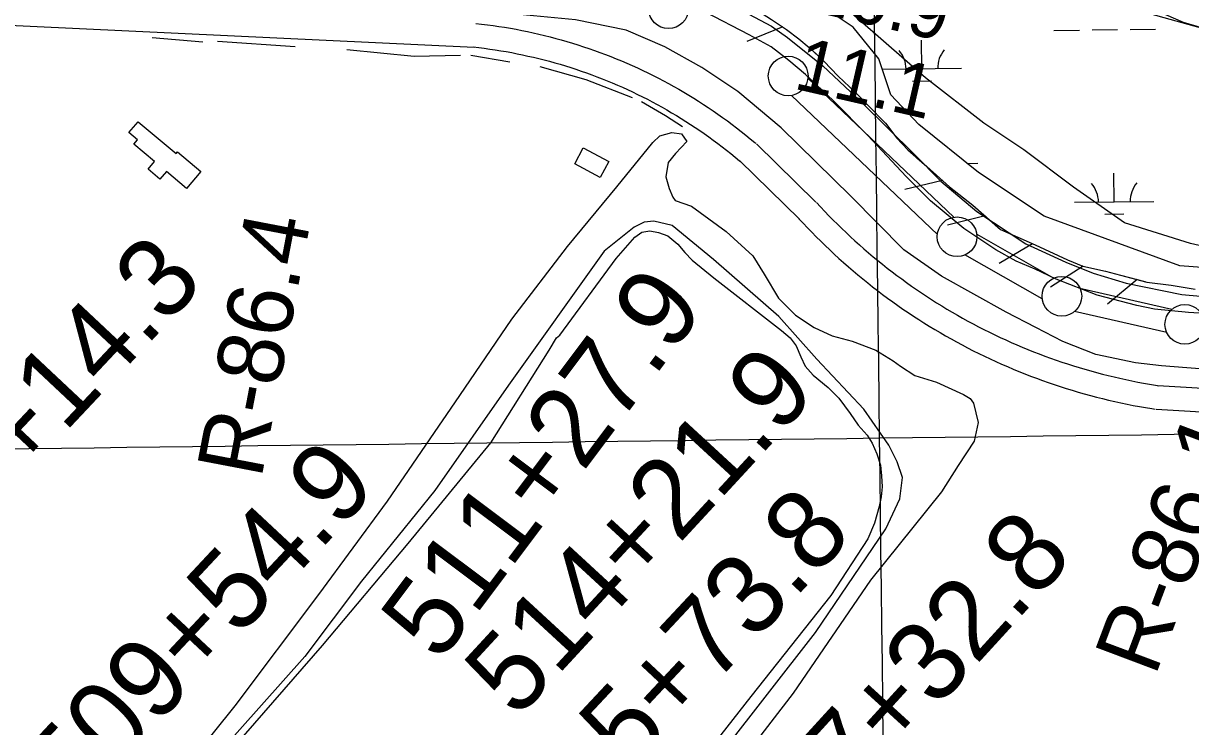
# Model space of a CAD drawing. Extents: x 3704301 to 3742427, y 506229 to 532009.
# Drawn here: x 3723258 to 3724729, y 517533 to 518420 of the extents above; entities that cross this region are included whole.
import ezdxf

# ---------------------------------------------------------------- set-up
doc = ezdxf.new("R2010")
doc.units = 0
for name, color, linetype in [('V-BLDG-OTLN', 7, 'Continuous'), ('V-FLOD-BASE', 7, 'Continuous'), ('V-GRID-MAJR', 7, 'Continuous'), ('V-LEVE-TOET', 7, 'Continuous'), ('V-RIVR-RANG', 7, 'Continuous'), ('V-RIVR-RANG-IDEN', 7, 'Continuous'), ('V-ROAD-CNTR', 7, 'Continuous'), ('V-RRAP-FSHR', 7, 'Continuous'), ('V-SITE-VEGE', 7, 'Continuous'), ('V-SURV-IDEN', 7, 'Continuous'), ('V-SURV-LINE', 7, 'Continuous'), ('V-TOPO-SHOR', 7, 'Continuous'), ('V-WETL-SWMP', 7, 'Continuous')]:
    doc.layers.add(name, color=color, linetype=linetype)

msp = doc.modelspace()

# ---------------------------------------------------------------- linework, layer by layer
at = {"layer": 'V-BLDG-OTLN'}
for points in [[(3723452.231, 518257.636), (3723481.544, 518232.97000000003), (3723463.593, 518211.63800000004), (3723438.376, 518232.86), (3723430.1210000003, 518223.048), (3723415.097, 518235.69200000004), (3723423.432, 518245.596), (3723397.384, 518267.518), (3723401.918, 518272.902), (3723391.08, 518282.022), (3723402.6350000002, 518295.75200000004), (3723450.4450000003, 518255.515)], [(3723963.7290000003, 518262.80100000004), (3723995.7290000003, 518245.715), (3723984.881, 518225.39900000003), (3723952.881, 518242.485)]]:
    msp.add_lwpolyline(points, close=True, dxfattribs=at)
at = {"layer": 'V-FLOD-BASE'}
msp.add_lwpolyline([(3724820.361, 518049.058), (3724726.697, 518055.04600000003), (3724683.724, 518059.281), (3724661.614, 518063.777), (3724611.377, 518076.86100000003), (3724559.861, 518097.085), (3724533.473, 518109.871), (3724509.507, 518119.708), (3724483.694, 518134.289), (3724443.418, 518161.21), (3724401.262, 518195.856), (3724370.481, 518226.472), (3724322.148, 518278.327), (3724278.679, 518322.496), (3724243.6950000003, 518355.443), (3724222.613, 518373.064), (3724200.345, 518390.074), (3724172.736, 518405.23000000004), (3724117.538, 518433.754)], dxfattribs=at)
at = {"layer": 'V-GRID-MAJR'}
for points in [[(3724411.217, 511839.73000000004), (3724337.211, 517896.76900000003), (3724263.162, 523957.275), (3724189.114, 530017.796), (3724189.072, 530021.25)], [(3708498.534, 517706.704), (3713778.102, 517769.291), (3719057.661, 517832.646), (3724337.211, 517896.76900000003), (3729616.752, 517961.659), (3734896.2830000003, 518027.318), (3740175.804, 518093.744), (3740175.805, 518093.744)]]:
    msp.add_spline(points, degree=3, dxfattribs=at)
at = {"layer": 'V-LEVE-TOET'}
for points in [[(3723241.023, 518548.99700000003), (3723399.696, 518540.24), (3723580.989, 518534.147), (3723761.02, 518523.86600000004), (3723846.936, 518517.77900000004), (3723929.855, 518512.85000000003), (3723964.483, 518508.51), (3723996.7430000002, 518502.952), (3724037.412, 518492.13), (3724078.714, 518478.337), (3724135.684, 518451.02900000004), (3724201.095, 518416.074), (3724220.9420000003, 518402.014), (3724265.498, 518366.205)], [(3724831.0330000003, 517976.94200000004), (3724692.602, 517987.739), (3724659.769, 517991.505), (3724609.562, 518002.206), (3724568.231, 518018.385), (3724534.077, 518036.147), (3724496.879, 518055.35500000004), (3724415.244, 518100.837), (3724367.736, 518134.226), (3724300.728, 518201.945), (3724213.225, 518287.889), (3724158.4080000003, 518333.70300000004), (3724113.323, 518364.143), (3724066.5, 518390.386), (3724017.9560000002, 518411.24), (3723954.014, 518424.157), (3723865.683, 518432.597), (3723729.741, 518435.079), (3723574.071, 518442.087), (3723411.247, 518449.006), (3723312.265, 518451.353), (3723185.225, 518456.927)], [(3724265.498, 518366.205), (3724314.353, 518320.315), (3724381.339, 518254.384), (3724414.543, 518220.819), (3724459.724, 518182.634), (3724521.633, 518141.674), (3724571.9960000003, 518118.456), (3724606.265, 518104.577), (3724648.148, 518091.982), (3724718.0670000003, 518077.949), (3724798.037, 518070.597), (3724933.466, 518061.55100000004), (3725125.861, 518054.284), (3725305.761, 518044.956), (3725459.773, 518037.212), (3725587.4080000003, 518031.646), (3725746.0810000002, 518022.886), (3725925.011, 518014.977), (3725985.8340000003, 518013.349)]]:
    msp.add_lwpolyline(points, dxfattribs=at)
at = {"layer": 'V-ROAD-CNTR'}
for points in [[(3722128.416704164, 518470.75203230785), (3722271.2194185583, 518463.91704597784), (3723825.9983089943, 518389.90419400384)], [(3723828.404304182, 518419.7911342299), (3723835.593289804, 518418.9751358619), (3723842.8572752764, 518418.0671376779), (3723850.107260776, 518417.077139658), (3723857.348246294, 518416.0081417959), (3723864.576231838, 518414.85614409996), (3723871.788217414, 518413.6251465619), (3723878.9902030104, 518412.3131491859), (3723886.17518864, 518410.9201519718), (3723893.343174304, 518409.447154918), (3723900.497159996, 518407.893158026), (3723907.63014573, 518406.26016129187), (3723914.7451315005, 518404.548164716), (3723921.842117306, 518402.75616829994), (3723928.9181031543, 518400.8841720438), (3723935.9710890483, 518398.933175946), (3723943.002074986, 518396.9041800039), (3723950.0110609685, 518394.7961842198), (3723956.9970469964, 518392.610188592), (3723963.9560330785, 518390.34519312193), (3723970.8890192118, 518388.00419780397), (3723977.796005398, 518385.5842026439), (3723984.6769916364, 518383.0882076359), (3723991.527977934, 518380.5152127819), (3723998.351964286, 518377.865218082), (3724005.1429507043, 518375.138223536), (3724011.9029371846, 518372.338229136), (3724018.6339237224, 518369.4602348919), (3724025.330910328, 518366.50724079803), (3724031.993897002, 518363.4802468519), (3724038.6228837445, 518360.3792530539), (3724045.217870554, 518357.204259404), (3724051.7758574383, 518353.954265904), (3724058.2968443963, 518350.6332725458), (3724064.7788314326, 518347.23827933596), (3724071.2248185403, 518343.772286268), (3724077.6318057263, 518340.2322933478), (3724083.998792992, 518336.62130057), (3724090.323780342, 518332.9403079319), (3724096.6077677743, 518329.1883154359), (3724102.848755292, 518325.36632307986), (3724109.046742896, 518321.474330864), (3724115.201730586, 518317.5133387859), (3724121.3107183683, 518313.48434684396), (3724127.3757062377, 518309.38735503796), (3724133.3946942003, 518305.22136336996), (3724139.3656822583, 518300.9893718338), (3724145.287670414, 518296.69138043), (3724151.162658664, 518292.32638915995), (3724156.988647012, 518287.89639802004), (3724162.76463546, 518283.40140700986), (3724168.48962401, 518278.8424161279), (3724174.1636126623, 518274.21842537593), (3724179.758601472, 518269.55443470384), (3724181.0385989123, 518268.47343686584)], [(3723825.0183109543, 518389.983193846), (3723832.0392969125, 518389.185195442), (3723838.967283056, 518388.31919717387), (3723845.887269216, 518387.3751990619), (3723852.796255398, 518386.3542011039), (3723859.692241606, 518385.2562033), (3723866.576227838, 518384.0812056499), (3723873.446214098, 518382.829208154), (3723880.301200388, 518381.50021081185), (3723887.141186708, 518380.09521362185), (3723893.9651730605, 518378.6132165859), (3723900.772159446, 518377.05421970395), (3723907.5631458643, 518375.42022297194), (3723914.332132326, 518373.710226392), (3723921.082118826, 518371.92422996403), (3723927.813105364, 518370.06323368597), (3723934.524091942, 518368.12623755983), (3723941.211078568, 518366.11624158), (3723947.8730652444, 518364.03024575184), (3723954.514051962, 518361.8692500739), (3723961.1310387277, 518359.63425454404), (3723967.7220255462, 518357.32625915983), (3723974.287012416, 518354.9442639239), (3723980.823999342, 518352.4892688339), (3723987.3319863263, 518349.96127389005), (3723993.812973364, 518347.36027909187), (3724000.2649604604, 518344.6862844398), (3724006.685947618, 518341.942289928), (3724013.07493484, 518339.12529556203), (3724019.433922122, 518336.2363013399), (3724025.7589094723, 518333.27730725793), (3724032.0498968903, 518330.24831331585), (3724038.3058843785, 518327.148319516), (3724044.528871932, 518323.9773258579), (3724050.7168595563, 518320.73833233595), (3724056.866847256, 518317.4303389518), (3724062.9778350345, 518314.05434570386), (3724069.052822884, 518310.6093525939), (3724075.087810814, 518307.09635961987), (3724081.0837988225, 518303.5163667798), (3724087.038786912, 518299.8703740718), (3724092.952775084, 518296.1563815), (3724098.8257633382, 518292.3773890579), (3724104.6547516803, 518288.53239674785), (3724110.4417401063, 518284.62340456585), (3724116.1827286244, 518280.649412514), (3724121.87971723, 518276.6114205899), (3724127.531705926, 518272.5094287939), (3724133.1386947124, 518268.34443712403), (3724138.6966835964, 518264.11844557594), (3724144.2066725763, 518259.829454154), (3724149.6696616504, 518255.47846285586), (3724155.0836508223, 518251.06847167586), (3724160.4726400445, 518246.57448066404), (3724161.6786376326, 518245.55548270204)], [(3724181.8415973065, 518267.7434383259), (3724256.98944701, 518194.3175851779)], [(3724160.8756392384, 518246.28548124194), (3724236.023488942, 518172.85962809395)], [(3724257.513445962, 518193.778586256), (3724262.7364355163, 518188.13659753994), (3724267.9644250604, 518182.6066085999), (3724273.251414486, 518177.12861955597), (3724278.592403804, 518171.70563040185), (3724283.988393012, 518166.3376411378), (3724289.441382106, 518161.02665175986), (3724294.948371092, 518155.770662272), (3724300.508359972, 518150.572672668), (3724306.1213487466, 518145.43168295), (3724311.786337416, 518140.3496931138), (3724317.505325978, 518135.32570316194), (3724323.275314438, 518130.36071309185), (3724329.0953027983, 518125.45572290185), (3724334.965291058, 518120.61173258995), (3724340.887279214, 518115.82674215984), (3724346.8562672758, 518111.103751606), (3724352.8732552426, 518106.44276092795), (3724358.938243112, 518101.84477012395), (3724365.051230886, 518097.30777919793), (3724371.210218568, 518092.83478814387), (3724377.41420616, 518088.42579696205), (3724383.66419366, 518084.0808056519), (3724389.9581810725, 518079.79881421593), (3724396.295168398, 518075.584822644), (3724402.676155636, 518071.4348309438), (3724409.09914279, 518067.35083911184), (3724415.56412986, 518063.33284714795), (3724422.071116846, 518059.38185504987), (3724428.617103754, 518055.497862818), (3724435.203090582, 518051.68287044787), (3724441.828077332, 518047.934877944), (3724448.491064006, 518044.25588530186), (3724455.193050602, 518040.6438925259), (3724461.9300371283, 518037.10189960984), (3724468.703023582, 518033.63090655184), (3724475.512009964, 518030.22891335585), (3724482.356996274, 518026.89792001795), (3724489.2349825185, 518023.6369265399), (3724496.1449686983, 518020.4459329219), (3724503.087954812, 518017.32793915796), (3724510.064940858, 518014.2819452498), (3724517.070926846, 518011.30595120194), (3724524.106912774, 518008.403957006), (3724531.1728986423, 518005.5749626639), (3724538.267884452, 518002.8179681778), (3724545.391870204, 518000.13397354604), (3724552.540855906, 517997.52297876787), (3724559.7168415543, 517994.98798383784), (3724566.9198271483, 517992.52398876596), (3724574.1478126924, 517990.1369935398), (3724581.3997981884, 517987.822998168), (3724588.672783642, 517985.584002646), (3724595.970769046, 517983.42100697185), (3724603.291754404, 517981.333011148), (3724610.6317397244, 517979.32001517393), (3724617.9937250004, 517977.38301904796), (3724625.3737102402, 517975.52202276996), (3724632.772695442, 517973.73702634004), (3724640.189680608, 517972.02902975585), (3724647.6256657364, 517970.39703302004), (3724655.076650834, 517968.8410361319), (3724662.5426359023, 517967.3620390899), (3724670.0246209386, 517965.96104189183), (3724677.519605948, 517964.63604454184), (3724685.045590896, 517963.3860470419), (3724689.196582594, 517962.7300483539)], [(3724235.4994899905, 518173.3986270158), (3724240.828479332, 518167.6426385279), (3724246.2704684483, 518161.88465004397), (3724251.76945745, 518156.1866614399), (3724257.3264463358, 518150.5436727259), (3724262.9444351, 518144.957683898), (3724268.6174237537, 518139.430694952), (3724274.3464122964, 518133.9627058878), (3724280.1324007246, 518128.5527167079), (3724285.973389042, 518123.20372740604), (3724291.8703772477, 518117.9137379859), (3724297.821365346, 518112.68574844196), (3724303.8253533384, 518107.5207587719), (3724309.8813412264, 518102.41576898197), (3724315.9913290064, 518097.37377906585), (3724322.151316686, 518092.3967890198), (3724328.362304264, 518087.4817988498), (3724334.625291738, 518082.630808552), (3724340.936279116, 518077.84481812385), (3724347.2972663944, 518073.1258275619), (3724353.70425358, 518068.4708368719), (3724360.162240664, 518063.88184605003), (3724366.6642276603, 518059.3608550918), (3724373.21421456, 518054.90686399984), (3724379.8092013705, 518050.51887277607), (3724386.4501880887, 518046.200881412), (3724393.133174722, 518041.9508899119), (3724399.8621612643, 518037.7708982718), (3724406.631147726, 518033.6599064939), (3724413.443134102, 518029.61791457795), (3724420.2971203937, 518025.64692251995), (3724427.1901066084, 518021.74693032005), (3724434.1250927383, 518017.91793797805), (3724441.097078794, 518014.1619454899), (3724448.108064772, 518010.47595286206), (3724455.1570506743, 518006.862960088), (3724462.2440365, 518003.3229671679), (3724469.365022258, 517999.85597410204), (3724476.521007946, 517996.4629808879), (3724483.7129935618, 517993.14398752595), (3724490.939979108, 517989.89799401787), (3724498.196964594, 517986.72800035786), (3724505.4869500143, 517983.63200654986), (3724512.8109353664, 517980.61201258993), (3724520.162920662, 517977.66701847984), (3724527.5459058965, 517974.79802421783), (3724534.957891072, 517972.00602980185), (3724542.39887619, 517969.2890352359), (3724549.866861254, 517966.650040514), (3724557.361846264, 517964.0880456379), (3724564.8818312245, 517961.60305060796), (3724572.427816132, 517959.195055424), (3724579.99880099, 517956.866060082), (3724587.5927858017, 517954.615064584), (3724595.209770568, 517952.44106893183), (3724602.847755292, 517950.34807311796), (3724610.5077399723, 517948.33107715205), (3724618.187724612, 517946.39408102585), (3724625.8887092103, 517944.53708473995), (3724633.6076937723, 517942.7590882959), (3724641.3436783, 517941.06109169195), (3724649.0966627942, 517939.44309492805), (3724656.866647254, 517937.904098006), (3724664.650631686, 517936.445100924), (3724672.451616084, 517935.0661036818), (3724680.247600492, 517933.77210626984), (3724684.5165919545, 517933.0981076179)], [(3724687.7395855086, 517962.888048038), (3726081.298798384, 517880.6832124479)], [(3724685.97358904, 517932.940107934), (3726079.5328019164, 517850.7352723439)]]:
    msp.add_lwpolyline(points, dxfattribs=at)
at = {"layer": 'V-RRAP-FSHR'}
for p, q in [((3724215.167, 518415.248), (3724169.8370000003, 518397.091)), ((3724416.396, 518221.53500000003), (3724368.9280000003, 518210.08)), ((3724470.2490000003, 518176.853), (3724422.832, 518165.191)), ((3724529.991, 518141.77900000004), (3724488.088, 518116.707)), ((3724593.961, 518113.378), (3724552.744, 518087.193)), ((3724661.9250000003, 518096.65), (3724624.4050000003, 518065.398))]:
    msp.add_line(p, q, dxfattribs=at)
for points in [[(3723849.394, 518523.463), (3723866.684, 518522.625), (3723914.3200000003, 518520.318), (3723937.091, 518519.21400000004), (3723967.9, 518516.148), (3723995.453, 518510.87700000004), (3724027.5160000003, 518501.191), (3724061.6210000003, 518490.357), (3724087.9250000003, 518480.949), (3724126.936, 518463.056), (3724155.257, 518451.977), (3724183.338, 518435.925), (3724200.8910000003, 518424.58), (3724219.963, 518412.113), (3724235.384, 518400.085), (3724248.5, 518389.218), (3724257.92, 518380.397)], [(3724200.8910000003, 518424.58), (3724219.963, 518412.113), (3724235.384, 518400.085), (3724248.5, 518389.218), (3724266.8200000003, 518372.064), (3724285.052, 518353.079), (3724306.387, 518333.156), (3724322.377, 518316.64), (3724344.632, 518294.049), (3724358.9250000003, 518274.992), (3724372.649, 518260.423), (3724396.537, 518239.064), (3724425.47, 518213.526), (3724454.5300000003, 518190.606), (3724489.7660000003, 518159.778), (3724533.162, 518140.36), (3724574.2290000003, 518121.58), (3724593.517, 518113.56200000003), (3724621.805, 518107.207), (3724640.983, 518102.343), (3724673.869, 518093.403), (3724704.901, 518089.539), (3724735.098, 518084.66500000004)], [(3724384.328, 518249.98000000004), (3724396.537, 518239.064), (3724425.47, 518213.526), (3724454.5300000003, 518190.606), (3724489.7660000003, 518159.778), (3724533.162, 518140.36), (3724574.2290000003, 518121.58), (3724593.517, 518113.56200000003), (3724621.805, 518107.207), (3724640.983, 518102.343), (3724671.312, 518094.098)]]:
    msp.add_lwpolyline(points, dxfattribs=at)
at = {"layer": 'V-SITE-VEGE'}
for points in [[(3723209.889, 518704.012), (3723322.429, 518682.541), (3723410.958, 518669.088), (3723489.927, 518672.147), (3723554.447, 518666.712), (3723643.912, 518661.588), (3723760.455, 518652.63800000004), (3723842.719, 518641.188), (3723913.541, 518630.632), (3723999.9790000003, 518618.193), (3724073.918, 518607.67600000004), (3724114.571, 518598.825), (3724184.367, 518587.217), (3724264.6950000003, 518564.304), (3724313.7430000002, 518549.32300000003), (3724358.6410000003, 518533.248), (3724398.282, 518522.306), (3724436.8540000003, 518513.427), (3724525.526, 518488.54000000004), (3724602.74, 518465.59), (3724668.506, 518443.537), (3724719.72, 518421.304), (3724754.149, 518411.337)], [(3724788.645, 518128.38300000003), (3724729.218, 518142.197), (3724645.7320000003, 518168.188), (3724581.758, 518213.13300000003), (3724518.801, 518260.172), (3724468.481, 518293.851), (3724395.003, 518351.152), (3724259.424, 518470.05700000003)], [(3723417.538, 517424.526), (3723524.972, 517559.016), (3723630.573, 517699.347), (3723717.097, 517817.152), (3723808.122, 517950.266), (3723873.793, 518046.694), (3723943.983, 518138.488), (3724005.812, 518213.75200000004), (3724051.46, 518269.457), (3724060.153, 518277.778), (3724075.3510000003, 518282.07300000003), (3724087.691, 518280.467), (3724094.2630000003, 518270.57800000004), (3724079.785, 518255.732), (3724070.541, 518244.472), (3724067.833, 518226.255), (3724072.122, 518211.642), (3724076.365, 518200.55), (3724079.347, 518196.481), (3724099.97, 518189.112), (3724143.771, 518157.395), (3724177.237, 518126.603), (3724191.723, 518103.322), (3724209.811, 518073.277), (3724231.194, 518051.841), (3724254.734, 518036.295), (3724277.276, 518025.43), (3724302.8170000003, 518018.706), (3724332.287, 518007.342), (3724354.3910000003, 517994.126), (3724363.509, 517987.202), (3724381.6010000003, 517975.694), (3724408.807, 517967.234), (3724442.904, 517951.7), (3724451.182, 517946.525), (3724455.36, 517940.71), (3724461.531, 517916.153), (3724456.544, 517892.625), (3724436.398, 517861.875), (3724415.102, 517828.761), (3724325.568, 517717.37), (3724228.2060000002, 517574.794), (3724115.64, 517428.51)], [(3724138.219, 517499.766), (3724256.583, 517651.402), (3724345.059, 517782.01900000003), (3724362.774, 517819.78), (3724365.9590000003, 517846.803), (3724359.2600000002, 517866.66500000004), (3724349.026, 517887.653), (3724317.3740000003, 517933.014), (3724257.929, 517996.211), (3724210.3310000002, 518050.174), (3724127.9050000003, 518121.885), (3724075.755, 518164.645), (3724052.809, 518170.228), (3724040.507, 518168.89900000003), (3724027.674, 518162.873), (3723989.927, 518132.489), (3723869.435, 517963.228), (3723776.642, 517830.68200000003), (3723684.21, 517716.321), (3723612.657, 517620.993), (3723503.318, 517498.211)]]:
    msp.add_lwpolyline(points, dxfattribs=at)
at = {"layer": 'V-SURV-LINE'}
for points in [[(3724246.7493300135, 518350.4749851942), (3724430.7269876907, 518175.2461063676)], [(3724410.0470900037, 518153.51267492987), (3724226.0694324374, 518328.74155364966)], [(3724459.629342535, 518153.7690469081), (3724556.936045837, 518098.445378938)], [(3724542.110887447, 518072.36445322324), (3724444.804184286, 518127.6881211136)], [(3724589.7060667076, 518085.7023086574), (3724705.727356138, 518059.170699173)], [(3724699.0574032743, 518029.92156138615), (3724583.036113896, 518056.4531708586)]]:
    msp.add_lwpolyline(points, dxfattribs=at)
for centre in [(3724071.19771, 518438.1883599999), (3724221.94187, 518353.38779999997), (3724434.85455, 518150.59986000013), (3724566.88568, 518075.53363999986), (3724721.87779, 518040.09023000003)]:
    msp.add_circle(centre, 25, dxfattribs=at)
at = {"layer": 'V-TOPO-SHOR'}
for p, q in [((3723484.078, 518396.09500000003), (3723420.125, 518401.652)), ((3723600.34, 518390.068), (3723502.7490000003, 518396.702)), ((3723871.057, 518371.018), (3723822.014, 518379.374))]:
    msp.add_line(p, q, dxfattribs=at)
for points in [[(3723808.9390000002, 518379.212), (3723750.514, 518377.919), (3723665.764, 518386.398)], [(3724025.913, 518325.87), (3723967.2970000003, 518348.68200000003), (3723909.24, 518364.767)], [(3724088.661, 518289.284), (3724067.202, 518303.21), (3724037.183, 518320.778)], [(3723934.031, 518026.593), (3724004.97, 518123.265), (3724028.878, 518150.172), (3724037.6720000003, 518156.193), (3724047.701, 518158.091), (3724058.3740000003, 518155.859), (3724070.25, 518151.867), (3724082.796, 518141.38), (3724091.7970000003, 518130.849), (3724100.79, 518120.908), (3724128.2660000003, 518098.77900000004), (3724213.645, 518032.43200000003), (3724224.4050000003, 518023.106), (3724232.216, 518013.15), (3724237.713, 517999.027), (3724243.181, 517987.27), (3724253.372, 517976.161), (3724272.488, 517960.435), (3724285.663, 517946.998), (3724300.095, 517927.66500000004), (3724310.329, 517913.009), (3724321.724, 517900.142), (3724327.761, 517890.166), (3724333.842, 517876.641), (3724338.157, 517862.503), (3724339.509, 517848.919), (3724340.268, 517835.32800000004), (3724339.247, 517822.30700000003), (3724336.4390000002, 517810.447), (3724330.79, 517789.091), (3724322.164, 517769.469), (3724275.75, 517697.936), (3724175.036, 517570.737), (3724088.895, 517460.276)], [(3723524.204, 517507.659), (3723634.968, 517634.983), (3723742.764, 517763.452), (3723847.024, 517890.694), (3723920.668, 518007.506), (3723929.937, 518022.995), (3723934.031, 518026.593)]]:
    msp.add_lwpolyline(points, dxfattribs=at)
at = {"layer": 'V-WETL-SWMP'}
for p, q in [((3724556.9847382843, 518410.97731904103), (3724588.9823499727, 518411.3682746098)), ((3724604.981155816, 518411.56375239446), (3724636.978767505, 518411.954707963)), ((3724652.9775733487, 518412.15018574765), (3724684.9751850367, 518412.5411413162)), ((3724390.500459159, 518362.5097030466), (3724390.0606341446, 518398.50701619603)), ((3724340.6364207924, 518361.9004505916), (3724440.496727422, 518363.1205711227)), ((3724378.689880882, 518346.933246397), (3724402.6880896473, 518347.226463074)), ((3724447.6355202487, 518243.1278327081), (3724461.1182485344, 518243.2925683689)), ((3724633.041395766, 518194.64738499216), (3724632.601570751, 518230.6446981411)), ((3724583.0451275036, 518194.03651691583), (3724683.0376640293, 518195.2582530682)), ((3724621.2308174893, 518179.0709283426), (3724645.2290262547, 518179.3641450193))]:
    msp.add_line(p, q, dxfattribs=at)
msp.add_lwpolyline([(3725217.679, 518076.063), (3724715.475, 518113.728), (3724544.7260000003, 518176.503), (3724461.863, 518231.746), (3724386.532, 518292.01), (3724351.378, 518329.675), (3724336.312, 518374.874), (3724303.668, 518415.05), (3724266.003, 518440.16000000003), (3724233.36, 518467.781), (3724208.25, 518505.447), (3724200.717, 518543.112), (3724218.294, 518560.689), (3724316.223, 518553.156), (3724378.9990000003, 518518.00200000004), (3724514.594, 518472.803), (3724604.99, 518452.715), (3724702.92, 518425.094), (3724775.74, 518405.006)], dxfattribs=at)
for centre, radius, start, end in [((3724335.255845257, 518362.3095478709), 35.24628790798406, 359.9282006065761, 41.47185893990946), ((3724445.7334713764, 518363.6593937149), 35.246287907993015, 139.92819760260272, 181.47185593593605), ((3724577.796781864, 518194.4472298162), 35.24628790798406, 359.9282006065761, 41.47185893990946), ((3724688.274407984, 518195.7970756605), 35.246287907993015, 139.92819760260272, 181.47185593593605)]:
    msp.add_arc(centre, radius, start, end, dxfattribs=at)

# ---------------------------------------------------------------- texts
at = {"layer": 'V-RIVR-RANG'}
for s, p in [('10.9', (3724246.920676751, 518435.89014014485)), ('11.1', (3724227.343468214, 518337.78238201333))]:
    msp.add_text(s, height=66.99999999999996, rotation=347.05832571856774, dxfattribs=at).set_placement(p)
at = {"layer": 'V-RIVR-RANG-IDEN'}
for s, height, rotation, p in [('R-86.4', 82.99999800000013, 79.17117467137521, (3723557.75856438, 517844.00756248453)), ('R-86.1', 82.999998, 69.33871362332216, (3724684.2989769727, 517594.749924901))]:
    msp.add_text(s, height=height, rotation=rotation, dxfattribs=at).set_placement(p)
at = {"layer": 'V-SURV-IDEN'}
for s, height, rotation, p in [('508+14.3', 99.99999999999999, 46.78672229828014, (3723103.647224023, 517683.0720789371)), ('511+27.9', 99.99999999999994, 53.153423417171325, (3723782.4589895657, 517611.78423742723)), ('514+21.9', 99.99999999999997, 47.31695203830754, (3723880.076058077, 517541.0102929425)), ('509+54.9', 100.00000000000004, 46.963160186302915, (3723323.501992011, 517424.3357370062)), ('515+73.8', 99.99999999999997, 46.933116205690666, (3723922.1203576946, 517364.26145268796)), ('517+32.8', 100.00000000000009, 47.63301814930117, (3724205.4372943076, 517331.814985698))]:
    msp.add_text(s, height=height, rotation=rotation, dxfattribs=at).set_placement(p)

doc.saveas('drawing.dxf')
